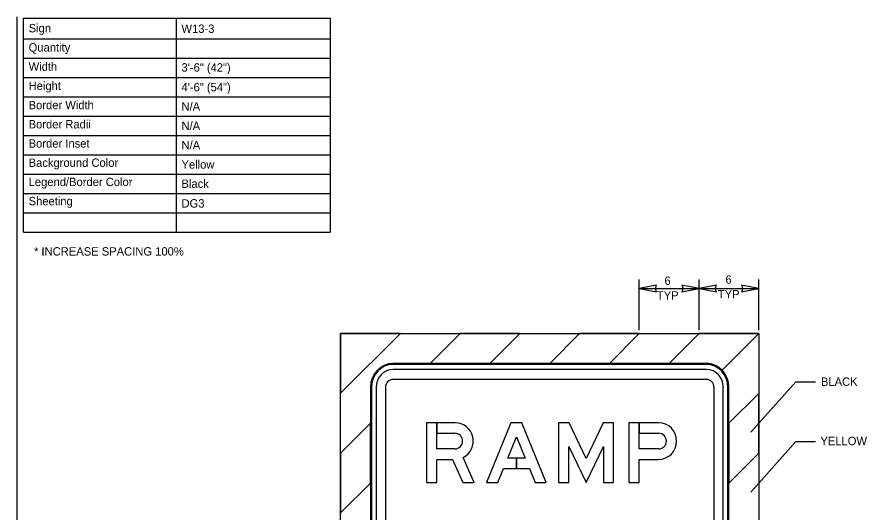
# Model space of a CAD drawing. Extents: x 582908 to 586041, y 1530940 to 1533040.
# Drawn here: x 584558 to 585981, y 1532211 to 1533040 of the extents above; entities that cross this region are included whole.
import ezdxf

# ---------------------------------------------------------------- set-up
doc = ezdxf.new("R2010")
doc.units = 0
for name, color, linetype in [('GSDims', 7, 'Continuous'), ('SheetLinesMisc2_dp', 7, 'Continuous'), ('SignPanel', 7, 'Continuous'), ('TextMisc', 7, 'Continuous'), ('TextNotes', 7, 'Continuous'), ('TextShtNo', 7, 'Continuous')]:
    doc.layers.add(name, color=color, linetype=linetype)

msp = doc.modelspace()

# ---------------------------------------------------------------- linework, layer by layer
at = {"layer": 'GSDims'}
for p, q in [((585600.1, 1532516.2), (585600.1, 1532600.9)), ((585700.1, 1532516.2), (585700.1, 1532600.9)), ((585800.1, 1532516.2), (585800.1, 1532600.9)), ((585629.1, 1532591.3), (585600.1, 1532585.9)), ((585600.1, 1532585.9), (585700.1, 1532585.9)), ((585600.1, 1532585.9), (585629.1, 1532580.3)), ((585626.9, 1532585.9), (585629.1, 1532591.3)), ((585629.1, 1532580.3), (585626.9, 1532585.9)), ((585700.1, 1532585.9), (585671.1, 1532591.5)), ((585671.1, 1532591.5), (585673.3, 1532585.9)), ((585673.3, 1532585.9), (585671.1, 1532580.5)), ((585671.1, 1532580.5), (585700.1, 1532585.9)), ((585729.1, 1532591.3), (585700.1, 1532585.9)), ((585700.1, 1532585.9), (585800.1, 1532585.9)), ((585700.1, 1532585.9), (585729.1, 1532580.3)), ((585726.9, 1532585.9), (585729.1, 1532591.3)), ((585729.1, 1532580.3), (585726.9, 1532585.9)), ((585800.1, 1532585.9), (585771.1, 1532591.5)), ((585771.1, 1532591.5), (585773.3, 1532585.9)), ((585773.3, 1532585.9), (585771.1, 1532580.5)), ((585771.1, 1532580.5), (585800.1, 1532585.9)), ((585786.8, 1532345.6), (585861.9, 1532430)), ((585861.9, 1532430), (585895, 1532430)), ((585786.8, 1532245.6), (585861.9, 1532330)), ((585861.9, 1532330), (585895, 1532330))]:
    msp.add_line(p, q, dxfattribs=at)
at = {"layer": 'SheetLinesMisc2_dp'}
for p, q in [((584558.3, 1533039.8), (584558.3, 1531119.8)), ((584569, 1532679.9), (584569, 1533037.8)), ((584569, 1533037.8), (585082.3, 1533037.8)), ((584824.9, 1533037.8), (584824.9, 1532679.9)), ((585082.3, 1533037.8), (585082.3, 1532679.9)), ((584569, 1533003.3), (585082.3, 1533003.3)), ((584569, 1532970.9), (585082.3, 1532970.9)), ((584569, 1532938.6), (585082.3, 1532938.6)), ((584569, 1532906.2), (585082.3, 1532906.2)), ((584569, 1532873.9), (585082.3, 1532873.9)), ((584569, 1532841.6), (585082.3, 1532841.6)), ((584569, 1532809.2), (585082.3, 1532809.2)), ((584569, 1532776.9), (585082.3, 1532776.9)), ((584569, 1532744.5), (585082.3, 1532744.5)), ((584569, 1532712.2), (585082.3, 1532712.2)), ((584569, 1532679.9), (585082.3, 1532679.9))]:
    msp.add_line(p, q, dxfattribs=at)
at = {"layer": 'SignPanel'}
for p, q in [((585200.1, 1532510.5), (585100.1, 1532510.5)), ((585712.6, 1532460.5), (585187.6, 1532460.5)), ((585187.6, 1532458.9), (585187.6, 1532458.8)), ((585712.6, 1532458.8), (585187.6, 1532458.8)), ((585712.6, 1532450.5), (585187.6, 1532450.5)), ((585712.6, 1532458.8), (585712.6, 1532458.9)), ((585712.6, 1532433.9), (585187.6, 1532433.9)), ((585150.1, 1532420.5), (585150.1, 1531700.6)), ((585150.1, 1532420.5), (585150.1, 1531700.6)), ((585151.6, 1532420.5), (585151.6, 1531700.6)), ((585151.6, 1532420.5), (585151.7, 1532420.5)), ((585159.5, 1532420.5), (585159.5, 1531700.6)), ((585175.1, 1532420.5), (585175.1, 1531700.6)), ((585725.1, 1531700.6), (585725.1, 1532420.5)), ((585740.7, 1531700.6), (585740.7, 1532420.5)), ((585748.5, 1532420.5), (585748.5, 1532420.5)), ((585748.5, 1531700.6), (585748.5, 1532420.5)), ((585750.1, 1531700.6), (585750.1, 1532420.5)), ((585291.4, 1532317.7), (585261.1, 1532317.7)), ((585632.5, 1532317.6), (585600, 1532317.6)), ((585600, 1532300.1), (585632.4, 1532300.1))]:
    msp.add_line(p, q, dxfattribs=at)
for points in [[(585200.1, 1532510.5), (585100.1, 1532510.5), (585100.1, 1532410.6), (585200.1, 1532510.5)], [(585250.1, 1532460.5), (585350.1, 1532460.5), (585400.1, 1532510.5), (585300.1, 1532510.5), (585250.1, 1532460.5)], [(585450.1, 1532460.5), (585550.1, 1532460.5), (585600.1, 1532510.5), (585500.1, 1532510.5), (585450.1, 1532460.5)], [(585738.7, 1532449.2), (585800.1, 1532510.5), (585700.1, 1532510.5), (585650.1, 1532460.5), (585712.6, 1532460.5)], [(585750.1, 1532360.5), (585750.1, 1532260.5), (585800.1, 1532310.5), (585800.1, 1532410.5), (585750.1, 1532360.5)], [(585100.1, 1532310.6), (585100.1, 1532210.6), (585150.1, 1532260.6), (585150.1, 1532360.6), (585100.1, 1532310.6)], [(585292, 1532361.3), (585243.8, 1532361.3), (585243.8, 1532261.3), (585261.1, 1532261.3), (585261.1, 1532300.2), (585287.6, 1532300.2)], [(585291.4, 1532317.7), (585261.1, 1532317.7), (585261.1, 1532361.3), (585243.8, 1532361.3), (585243.8, 1532261.3)], [(585291.4, 1532317.7), (585261.1, 1532317.7), (585261.1, 1532361.3), (585243.8, 1532361.3), (585243.8, 1532261.3)], [(585292, 1532361.3), (585261.1, 1532361.3), (585261.1, 1532343.8), (585291.4, 1532343.8)], [(585292, 1532361.3), (585261.1, 1532361.3), (585261.1, 1532343.8), (585291.4, 1532343.8)], [(585632.4, 1532361.3), (585582.8, 1532361.3), (585582.8, 1532261.3), (585600, 1532261.3), (585600, 1532300.1)], [(585600, 1532361.3), (585582.8, 1532361.3), (585582.8, 1532261.3), (585600, 1532261.3), (585600, 1532300.1), (585632.4, 1532300.1)], [(585600, 1532361.3), (585582.8, 1532361.3), (585582.8, 1532261.3), (585600, 1532261.3), (585600, 1532300.1), (585632.4, 1532300.1)], [(585632.4, 1532361.3), (585600, 1532361.3), (585600, 1532343.8), (585632.5, 1532343.8)], [(585632.5, 1532317.6), (585600, 1532317.6), (585600, 1532361.3)], [(585632.4, 1532361.3), (585600, 1532361.3), (585600, 1532343.8), (585632.5, 1532343.8)], [(585632.5, 1532317.6), (585600, 1532317.6), (585600, 1532361.3)], [(585261.1, 1532317.7), (585261.1, 1532343.8), (585291.4, 1532343.8)], [(585600, 1532317.6), (585600, 1532343.8), (585632.5, 1532343.8)], [(585243.8, 1532261.3), (585261.1, 1532261.3), (585261.1, 1532300.2), (585287.6, 1532300.2), (585304.7, 1532261.3), (585323.6, 1532261.3), (585305.2, 1532303.3)], [(585243.8, 1532261.3), (585261.1, 1532261.3), (585261.1, 1532300.2), (585287.6, 1532300.2), (585304.7, 1532261.3), (585323.6, 1532261.3), (585305.2, 1532303.3)], [(585287.6, 1532300.2), (585304.7, 1532261.3), (585323.6, 1532261.3), (585305.2, 1532303.3)]]:
    msp.add_lwpolyline(points, dxfattribs=at)
for points in [[(585100.1, 1532510.5), (585800.1, 1532510.5), (585800.1, 1531610.6), (585100.1, 1531610.6)], [(585416, 1532284.9), (585425.7, 1532261.3), (585444.3, 1532261.3), (585403.4, 1532361.3), (585385.2, 1532361.3), (585344.3, 1532261.3), (585363, 1532261.3), (585372.7, 1532284.9)], [(585372.7, 1532284.9), (585394.3, 1532284.9), (585394.3, 1532302.4), (585379.8, 1532302.4), (585394.3, 1532337.9), (585408.9, 1532302.4), (585394.3, 1532302.4), (585394.3, 1532284.9), (585416, 1532284.9), (585425.7, 1532261.3), (585444.3, 1532261.3), (585403.4, 1532361.3), (585385.2, 1532361.3), (585344.3, 1532261.3), (585363, 1532261.3)], [(585372.7, 1532284.9), (585394.3, 1532284.9), (585394.3, 1532302.4), (585379.8, 1532302.4), (585394.3, 1532337.9), (585408.9, 1532302.4), (585394.3, 1532302.4), (585394.3, 1532284.9), (585416, 1532284.9), (585425.7, 1532261.3), (585444.3, 1532261.3), (585403.4, 1532361.3), (585385.2, 1532361.3), (585344.3, 1532261.3), (585363, 1532261.3)], [(585482.3, 1532321.6), (585511.1, 1532261.3), (585539.9, 1532321.6), (585539.9, 1532261.3), (585557.1, 1532261.3), (585557.1, 1532361.3), (585539.8, 1532361.3), (585511.1, 1532301.4), (585482.4, 1532361.3), (585465, 1532361.3), (585465, 1532261.3), (585482.3, 1532261.3)], [(585482.3, 1532321.6), (585511.1, 1532261.3), (585539.9, 1532321.6), (585539.9, 1532261.3), (585557.1, 1532261.3), (585557.1, 1532361.3), (585539.8, 1532361.3), (585511.1, 1532301.4), (585482.4, 1532361.3), (585465, 1532361.3), (585465, 1532261.3), (585482.3, 1532261.3)], [(585482.3, 1532321.6), (585511.1, 1532261.3), (585539.9, 1532321.6), (585539.9, 1532261.3), (585557.1, 1532261.3), (585557.1, 1532361.3), (585539.8, 1532361.3), (585511.1, 1532301.4), (585482.4, 1532361.3), (585465, 1532361.3), (585465, 1532261.3), (585482.3, 1532261.3)], [(585394.3, 1532337.9), (585408.9, 1532302.4), (585379.8, 1532302.4)]]:
    msp.add_lwpolyline(points, close=True, dxfattribs=at)
for centre, major_axis, ratio, start_param, end_param in [((585187.6, 1532420.5), (0, 40), 0.937555, 0, 1.570796), ((585187.6, 1532420.5), (0, 40), 0.937555, 0, 1.570796), ((585187.6, 1532420.5), (0, 38.3), 0.937555, 0, 1.570796), ((585187.6, 1532420.5), (0, 30), 0.937555, 0, 1.570796), ((585712.6, 1532420.5), (0, 40), 0.937555, 4.712389, 6.283185), ((585712.6, 1532420.5), (0, 40), 0.937555, 5.51114, 6.283185), ((585712.6, 1532420.5), (0, 40), 0.937555, 4.712389, 6.283185), ((585712.6, 1532420.5), (0, 38.3), 0.937555, 4.712389, 6.283185), ((585712.6, 1532420.5), (0, 30), 0.937555, 4.712389, 6.283185), ((585187.6, 1532420.5), (0, 13.3), 0.937555, 0, 1.570796), ((585712.6, 1532420.5), (0, 13.3), 0.937555, 4.712389, 6.283185), ((585292, 1532330.8), (0, 30.6), 0.985, 3.595687, 6.283185), ((585292, 1532330.8), (0, 30.6), 0.985, 3.595687, 6.283185), ((585292, 1532330.8), (0, 30.6), 0.985, 3.595687, 6.283185), ((585632.4, 1532330.7), (0, 30.6), 0.985, 3.141593, 6.283185), ((585632.4, 1532330.7), (0, 30.6), 0.985, 3.141593, 6.283185), ((585632.4, 1532330.7), (0, 30.6), 0.985, 3.141593, 6.283185), ((585291.4, 1532330.8), (0, 13.1), 0.985, 3.141593, 6.283185), ((585291.4, 1532330.8), (0, 13.1), 0.985, 3.141593, 6.283185), ((585291.4, 1532330.8), (0, 13.1), 0.985, 3.141593, 6.283185), ((585632.5, 1532330.7), (0, 13.1), 0.985, 3.141593, 6.283185), ((585632.5, 1532330.7), (0, 13.1), 0.985, 3.141593, 6.283185), ((585632.5, 1532330.7), (0, 13.1), 0.985, 3.141593, 6.283185)]:
    msp.add_ellipse(centre, major_axis=major_axis, ratio=ratio, start_param=start_param, end_param=end_param, dxfattribs=at)

# ---------------------------------------------------------------- texts
at = {"layer": 'GSDims'}
for s, p in [('6', (585744.3, 1532593.9)), ('6', (585642.2, 1532591.9)), ('TYP', (585629.4, 1532567.4)), ('TYP', (585731.5, 1532569.4)), ('BLACK', (585904.1, 1532423.1)), ('YELLOW', (585903.2, 1532323.9))]:
    msp.add_text(s, height=14, dxfattribs=at).set_placement(p)
at = {"layer": 'TextMisc'}
for s, p in [('Sign', (584577.8, 1533014.2)), ('Quantity', (584577.8, 1532982)), ('Width', (584577.8, 1532949.9)), ('Height', (584577.8, 1532917.8)), ('Border Width', (584577.8, 1532885.6)), ('Border Radii', (584577.8, 1532853.5)), ('Border Inset', (584577.8, 1532821.4)), ('Background Color', (584577.8, 1532789.2)), ('Legend/Border Color', (584577.8, 1532757.1)), ('Sheeting', (584577.8, 1532725))]:
    msp.add_text(s, height=14, dxfattribs=at).set_placement(p)
at = {"layer": 'TextNotes'}
msp.add_text('* INCREASE SPACING 100%', height=14, dxfattribs=at).set_placement((584586.8, 1532640.9))
at = {"layer": 'TextShtNo'}
for s, p in [('W13-3', (584833.7, 1533013.2)), ('3\'-6" (42")', (584833.7, 1532948.5)), ('4\'-6" (54")', (584833.7, 1532915.6)), ('N/A', (584833.7, 1532883.2)), ('N/A', (584833.7, 1532850.9)), ('N/A', (584833.7, 1532818.6)), ('Yellow', (584833.7, 1532786.3)), ('Black', (584833.7, 1532754.1)), ('DG3', (584833.7, 1532721.2))]:
    msp.add_text(s, height=14, dxfattribs=at).set_placement(p)

doc.saveas('drawing.dxf')
